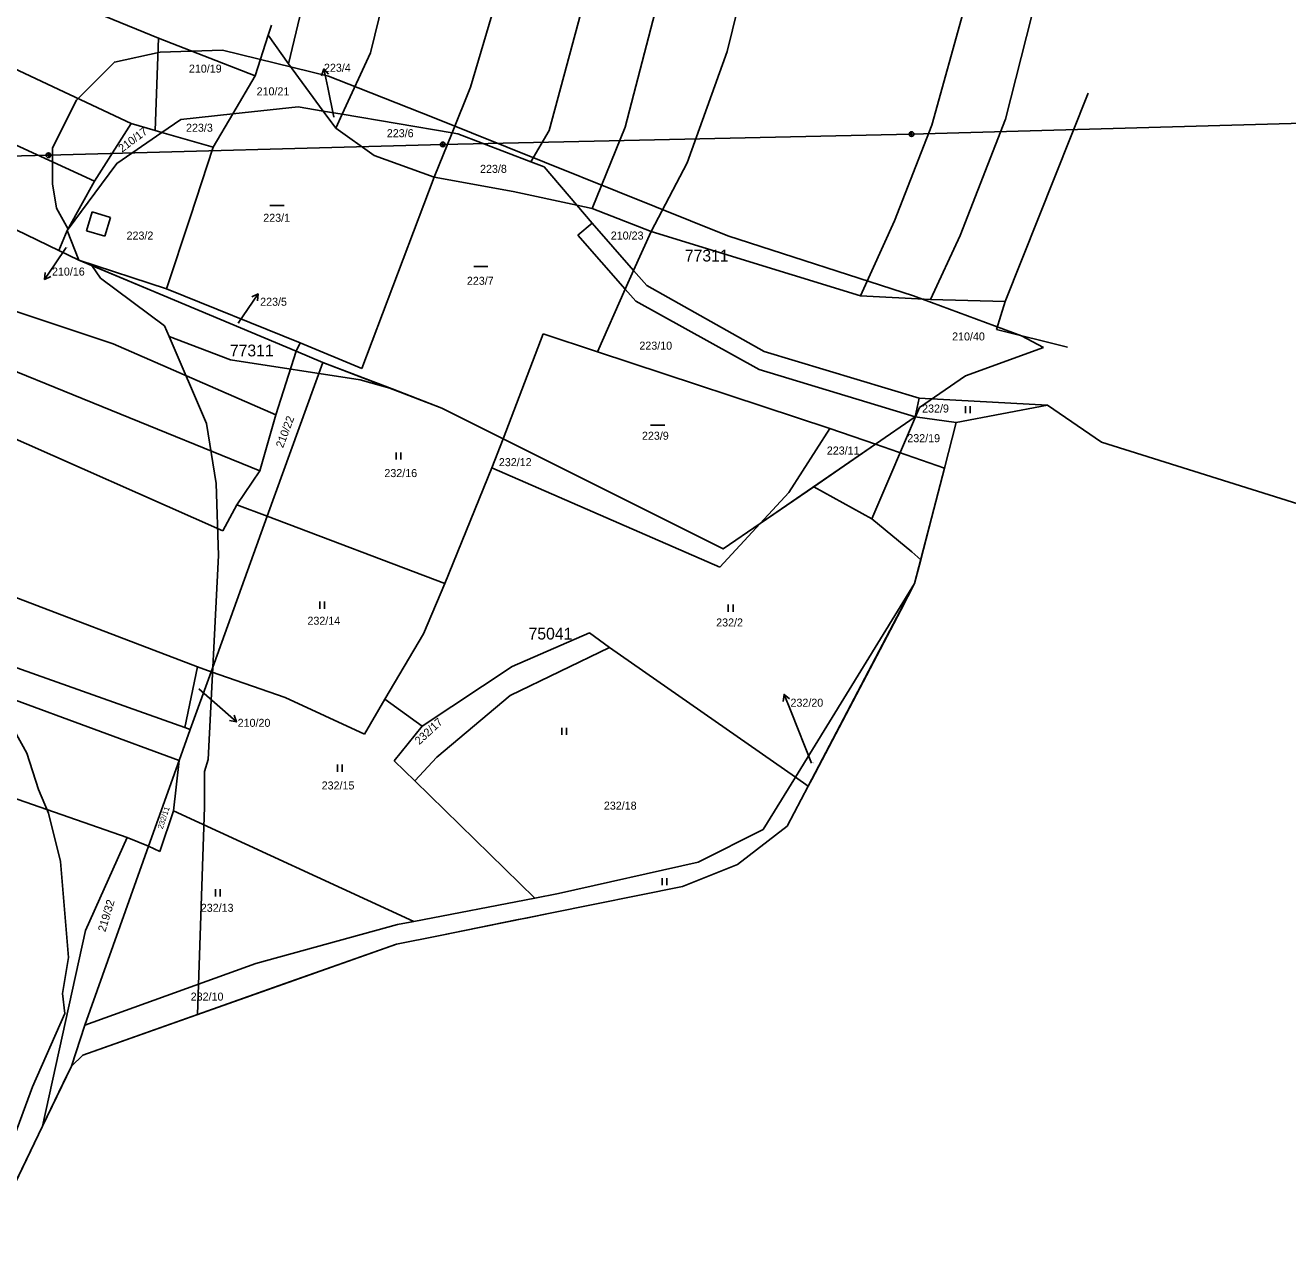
# Model space of a CAD drawing. Extents: x -743888 to -742027, y -1128394 to -1126768.
# Drawn here: x -742720.1 to -742452, y -1128049.6 to -1127789.2 of the extents above; entities that cross this region are included whole.
import ezdxf

# ---------------------------------------------------------------- set-up
doc = ezdxf.new("R2010")
doc.units = 0
for name, color, linetype in [('Vrstva 1', 7, 'Continuous'), ('Vrstva 12', 7, 'Continuous'), ('Vrstva 13', 7, 'Continuous'), ('Vrstva 16', 7, 'Continuous'), ('Vrstva 18', 7, 'Continuous'), ('Vrstva 25', 7, 'Continuous'), ('Vrstva 26', 7, 'Continuous'), ('Vrstva 4', 7, 'Continuous'), ('Vrstva 52', 7, 'Continuous'), ('Vrstva 53', 7, 'Continuous'), ('Vrstva 6', 7, 'Continuous')]:
    doc.layers.add(name, color=color, linetype=linetype)

msp = doc.modelspace()

# ---------------------------------------------------------------- linework, layer by layer
at = {"layer": 'Vrstva 1'}
for points in [[(-742675.99, -1127807.99), (-742662.11, -1127806.5)], [(-742662.11, -1127806.5), (-742656.82, -1127807.4)], [(-742691.07, -1127811.95), (-742687.04, -1127809.18)], [(-742687.04, -1127809.18), (-742675.99, -1127807.99)], [(-742656.82, -1127807.4), (-742652.76, -1127808.09)], [(-742652.76, -1127808.09), (-742629.43, -1127812.04)], [(-742700.65, -1127818.54), (-742691.07, -1127811.95)], [(-742629.43, -1127812.04), (-742628.23, -1127812.24)], [(-742628.23, -1127812.24), (-742612.72, -1127818.18)], [(-742703.9, -1127822.96), (-742700.65, -1127818.54)], [(-742612.72, -1127818.18), (-742609.89, -1127819.27)], [(-742609.89, -1127819.27), (-742602.93, -1127827.4)], [(-742711.14, -1127832.79), (-742703.9, -1127822.96)], [(-742602.93, -1127827.4), (-742599.66, -1127831.22)], [(-742711.14, -1127832.79), (-742708.67, -1127839.06)], [(-742599.66, -1127831.22), (-742590.87, -1127841.26)], [(-742708.67, -1127839.06), (-742690.54, -1127846.66)], [(-742590.87, -1127841.26), (-742588.09, -1127844.43)], [(-742588.09, -1127844.43), (-742563.17, -1127858.44)], [(-742690.54, -1127846.66), (-742662.54, -1127858.41)], [(-742662.54, -1127858.41), (-742656.86, -1127860.79)], [(-742563.17, -1127858.44), (-742530.23, -1127868.37)], [(-742668.67, -1127893.45), (-742656.86, -1127860.79)], [(-742656.86, -1127860.79), (-742631.6, -1127870.48)], [(-742531.05, -1127872.36), (-742530.23, -1127868.37)], [(-742530.23, -1127868.37), (-742503.01, -1127869.85)], [(-742631.6, -1127870.48), (-742618.61, -1127876.98)], [(-742539.51, -1127878.17), (-742531.05, -1127872.36)], [(-742531.05, -1127872.36), (-742522.38, -1127873.53)], [(-742618.61, -1127876.98), (-742571.86, -1127900.4)], [(-742564.03, -1127895.02), (-742539.51, -1127878.17)], [(-742680.6, -1127926.45), (-742668.67, -1127893.45)], [(-742571.86, -1127900.4), (-742564.03, -1127895.02)], [(-742802.25, -1127897.14), (-742686.17, -1127938.31)], [(-742556.49, -1127948.86), (-742531.2, -1127907.76)], [(-742685.04, -1127938.71), (-742680.6, -1127926.45)], [(-742686.17, -1127938.31), (-742685.04, -1127938.71)], [(-742687.4, -1127945.34), (-742685.04, -1127938.71)], [(-742693.88, -1127963.5), (-742687.4, -1127945.34)], [(-742563.33, -1127959.98), (-742556.49, -1127948.86)], [(-742577.15, -1127966.9), (-742563.33, -1127959.98)], [(-742707.43, -1128001.51), (-742693.88, -1127963.5)], [(-742606.85, -1127973.58), (-742577.15, -1127966.9)], [(-742637.54, -1127979.49), (-742611.87, -1127974.55)], [(-742611.87, -1127974.55), (-742606.85, -1127973.58)], [(-742671.12, -1127988.44), (-742641.03, -1127980.16)], [(-742641.03, -1127980.16), (-742637.54, -1127979.49)], [(-742707.43, -1128001.51), (-742671.12, -1127988.44)], [(-742710.24, -1128010.19), (-742707.43, -1128001.51)]]:
    msp.add_lwpolyline(points, dxfattribs=at)
at = {"layer": 'Vrstva 12'}
for points in [[(-742433.58, -1127809.53), (-742531.86, -1127812.3)], [(-742631.4, -1127814.49), (-742531.86, -1127812.3)], [(-742715.13, -1127816.8), (-742631.4, -1127814.49)], [(-742821.14, -1127819.37), (-742715.13, -1127816.8)]]:
    msp.add_lwpolyline(points, dxfattribs=at)
at = {"layer": 'Vrstva 13'}
for p, q in [((-742531.2, -1127907.76), (-742524.88, -1127883.24)), ((-742553.06, -1127949.33), (-742534.15, -1127913.36)), ((-742608.61, -1127977.73), (-742580.51, -1127972.05)), ((-742707.81, -1128007.87), (-742641.25, -1127984.32)), ((-742728.18, -1128047.33), (-742716.39, -1128022.92))]:
    msp.add_line(p, q, dxfattribs=at)
for points in [[(-742522.38, -1127873.53), (-742503.01, -1127869.85)], [(-742524.88, -1127883.24), (-742522.38, -1127873.53)], [(-742534.15, -1127913.36), (-742531.2, -1127907.76)], [(-742558.28, -1127959.25), (-742553.8, -1127950.73)], [(-742553.8, -1127950.73), (-742553.06, -1127949.33)], [(-742568.84, -1127967.38), (-742558.28, -1127959.25)], [(-742580.51, -1127972.05), (-742568.84, -1127967.38)], [(-742632.32, -1127982.52), (-742608.61, -1127977.73)], [(-742641.25, -1127984.32), (-742632.32, -1127982.52)], [(-742710.24, -1128010.19), (-742707.81, -1128007.87)], [(-742716.39, -1128022.92), (-742710.24, -1128010.19)]]:
    msp.add_lwpolyline(points, dxfattribs=at)
at = {"layer": 'Vrstva 16'}
for p, q in [((-742657.12, -1127799.9), (-742656.65, -1127798.47)), ((-742714.6, -1127842.52), (-742715.95, -1127843.17)), ((-742671.96, -1127846.87), (-742670.61, -1127846.22)), ((-742559.14, -1127932.75), (-742558.93, -1127931.27)), ((-742675.69, -1127935.7), (-742675.21, -1127937.12))]:
    msp.add_line(p, q, dxfattribs=at)
for points in [[(-742655.84, -1127802.39), (-742656.65, -1127798.47), (-742655.65, -1127799.59)], [(-742654.53, -1127808.7), (-742655.84, -1127802.39)], [(-742711.38, -1127836.41), (-742713.71, -1127839.86)], [(-742713.71, -1127839.86), (-742715.95, -1127843.17), (-742715.84, -1127841.68)], [(-742672.86, -1127849.53), (-742670.61, -1127846.22), (-742670.72, -1127847.72)], [(-742674.85, -1127852.46), (-742672.86, -1127849.53)], [(-742683.2, -1127930.09), (-742678.21, -1127934.48)], [(-742557.44, -1127934.98), (-742558.93, -1127931.27), (-742557.75, -1127932.19)], [(-742678.21, -1127934.48), (-742675.21, -1127937.12), (-742676.68, -1127936.83)], [(-742553.07, -1127945.89), (-742557.44, -1127934.98)]]:
    msp.add_lwpolyline(points, dxfattribs=at)
at = {"layer": 'Vrstva 25'}
for p, q in [((-742668.11, -1127827.45), (-742665.11, -1127827.45)), ((-742624.81, -1127840.39), (-742621.81, -1127840.39)), ((-742520.37, -1127870.09), (-742520.37, -1127871.59)), ((-742519.37, -1127871.59), (-742519.37, -1127870.09)), ((-742587.26, -1127874.09), (-742584.26, -1127874.09)), ((-742641.29, -1127879.92), (-742641.29, -1127881.42)), ((-742640.29, -1127881.42), (-742640.29, -1127879.92)), ((-742657.54, -1127911.58), (-742657.54, -1127913.08)), ((-742656.54, -1127913.08), (-742656.54, -1127911.58)), ((-742570.76, -1127912.21), (-742570.76, -1127913.71)), ((-742569.76, -1127913.71), (-742569.76, -1127912.21)), ((-742606.12, -1127938.36), (-742606.12, -1127939.86)), ((-742605.12, -1127939.86), (-742605.12, -1127938.36)), ((-742653.74, -1127946.19), (-742653.74, -1127947.69)), ((-742652.74, -1127947.69), (-742652.74, -1127946.19)), ((-742584.81, -1127970.31), (-742584.81, -1127971.81)), ((-742583.81, -1127971.81), (-742583.81, -1127970.31)), ((-742679.68, -1127972.66), (-742679.68, -1127974.16)), ((-742678.68, -1127974.16), (-742678.68, -1127972.66))]:
    msp.add_line(p, q, dxfattribs=at)
at = {"layer": 'Vrstva 26'}
for p, q in [((-742532.32, -1127812.48), (-742531.68, -1127811.84)), ((-742532.06, -1127812.75), (-742531.41, -1127812.1)), ((-742631.86, -1127814.67), (-742631.21, -1127814.03)), ((-742631.6, -1127814.94), (-742630.95, -1127814.29)), ((-742715.59, -1127816.98), (-742714.95, -1127816.34)), ((-742715.33, -1127817.25), (-742714.68, -1127816.6))]:
    msp.add_line(p, q, dxfattribs=at)
for centre in [(-742531.86, -1127812.3), (-742631.4, -1127814.49), (-742715.13, -1127816.8)]:
    msp.add_circle(centre, 0.5, dxfattribs=at)
at = {"layer": 'Vrstva 4'}
for points in [[(-742707.09, -1127832.82), (-742705.88, -1127828.82)], [(-742705.88, -1127828.82), (-742701.93, -1127830.01)], [(-742703.14, -1127834.01), (-742701.93, -1127830.01)], [(-742707.09, -1127832.82), (-742703.14, -1127834.01)], [(-742602.7, -1127833.78), (-742599.66, -1127831.22)], [(-742602.7, -1127833.78), (-742592.64, -1127845.23)], [(-742592.64, -1127845.23), (-742590.38, -1127847.8)], [(-742590.38, -1127847.8), (-742564.19, -1127862.31)], [(-742564.19, -1127862.31), (-742531.05, -1127872.36)]]:
    msp.add_lwpolyline(points, dxfattribs=at)
at = {"layer": 'Vrstva 52'}
for points in [[(-742503.81, -1127857.63), (-742508.5, -1127855.13), (-742531.44, -1127846.63), (-742570.88, -1127833.88), (-742633.25, -1127808.88), (-742649.38, -1127802.5), (-742655.69, -1127800), (-742678.19, -1127794.5), (-742691.38, -1127794.88), (-742701.13, -1127797), (-742709.19, -1127805.13), (-742714.25, -1127815.25), (-742714.25, -1127822.88), (-742713.44, -1127828), (-742710.93, -1127832.5)], [(-742710.93, -1127832.5), (-742703.9, -1127822.96), (-742700.65, -1127818.54), (-742691.07, -1127811.95), (-742687.04, -1127809.18), (-742675.99, -1127807.99), (-742662.11, -1127806.5), (-742656.82, -1127807.4), (-742652.76, -1127808.09), (-742629.43, -1127812.04), (-742628.23, -1127812.24), (-742612.72, -1127818.18), (-742609.89, -1127819.27), (-742602.93, -1127827.4), (-742599.66, -1127831.22), (-742590.87, -1127841.26), (-742588.09, -1127844.43), (-742563.17, -1127858.44), (-742530.23, -1127868.37), (-742531.05, -1127872.36), (-742539.51, -1127878.17), (-742552.6, -1127887.17)], [(-742710.93, -1127832.5), (-742711.14, -1127832.79), (-742708.67, -1127839.06), (-742705.95, -1127840.2)], [(-742705.95, -1127840.2), (-742704.06, -1127842.88), (-742690.5, -1127853), (-742689.53, -1127855.25)], [(-742705.95, -1127840.2), (-742690.54, -1127846.66), (-742662.54, -1127858.41), (-742656.86, -1127860.79), (-742642.18, -1127866.42)], [(-742689.53, -1127855.25), (-742676.5, -1127860.25), (-742648.94, -1127864.5), (-742642.18, -1127866.42)], [(-742683.48, -1127999.26), (-742682, -1127955.25), (-742682, -1127947.63), (-742681.19, -1127945.13), (-742679.06, -1127901.75), (-742679.5, -1127886.5), (-742681.56, -1127873.75), (-742689.53, -1127855.25)], [(-742540.25, -1127894), (-742530.13, -1127870.38), (-742520.38, -1127863.63), (-742503.81, -1127857.63)], [(-742642.18, -1127866.42), (-742631.6, -1127870.48), (-742618.61, -1127876.98), (-742571.86, -1127900.4), (-742564.03, -1127895.02), (-742552.6, -1127887.17)], [(-742529.9, -1127902.7), (-742524.88, -1127883.24), (-742522.38, -1127873.53), (-742503.01, -1127869.85), (-742491.5, -1127877.75), (-742426.38, -1127898.15), (-742397.46, -1127907.21), (-742391.19, -1127889.54)], [(-742552.6, -1127887.17), (-742540.25, -1127894)], [(-742540.25, -1127894), (-742531.81, -1127901), (-742529.9, -1127902.7)], [(-742683.48, -1127999.26), (-742666.12, -1127993.12), (-742641.25, -1127984.32), (-742632.32, -1127982.52), (-742615.39, -1127979.1), (-742613.69, -1127978.76), (-742608.61, -1127977.73), (-742580.51, -1127972.05), (-742575.53, -1127970.06), (-742568.84, -1127967.38), (-742558.28, -1127959.25), (-742553.8, -1127950.73), (-742531.2, -1127907.76), (-742529.9, -1127902.7)], [(-742725.31, -1127933.63), (-742719.75, -1127943.75), (-742717.25, -1127951.5), (-742715.13, -1127956.5), (-742712.56, -1127966.75), (-742710.88, -1127987.13), (-742712.13, -1127994.75), (-742711.69, -1127999), (-742718.5, -1128014.63), (-742722.75, -1128026.13)], [(-742729.71, -1128049.62), (-742728.18, -1128047.33), (-742716.39, -1128022.92), (-742711.15, -1128012.08), (-742710.24, -1128010.19), (-742707.81, -1128007.87), (-742683.48, -1127999.26)]]:
    msp.add_lwpolyline(points, dxfattribs=at)
at = {"layer": 'Vrstva 6'}
for points in [[(-742625.54, -1127802.36), (-742595.59, -1127701.21)], [(-742664.19, -1127797.36), (-742650.2, -1127739.03)], [(-742608.79, -1127811.54), (-742589.16, -1127738.55)], [(-742592.67, -1127810.85), (-742575.45, -1127744.63)], [(-742786.9, -1127753.03), (-742691.75, -1127791.9)], [(-742646.74, -1127795.08), (-742636.01, -1127751.08)], [(-742511.87, -1127809.1), (-742499.62, -1127760.84)], [(-742571.03, -1127794.76), (-742564.08, -1127766.54)], [(-742527.52, -1127810.4), (-742520.53, -1127785.2)], [(-742668.48, -1127791.31), (-742667.79, -1127789.16)], [(-742692.45, -1127811.55), (-742691.75, -1127791.9)], [(-742691.75, -1127791.9), (-742671.24, -1127799.9)], [(-742671.24, -1127799.9), (-742668.48, -1127791.31)], [(-742668.48, -1127791.31), (-742664.19, -1127797.36)], [(-742652.76, -1127808.09), (-742646.74, -1127795.08)], [(-742579.48, -1127818.4), (-742571.03, -1127794.76)], [(-742723.74, -1127797.75), (-742697.57, -1127810.08)], [(-742664.19, -1127797.36), (-742656.82, -1127807.4)], [(-742752.11, -1127800.85), (-742705.33, -1127822.31)], [(-742675.99, -1127807.99), (-742671.24, -1127799.9)], [(-742629.43, -1127812.04), (-742625.54, -1127802.36)], [(-742511.96, -1127847.84), (-742494.32, -1127803.6)], [(-742777.16, -1127805.95), (-742712.92, -1127837.01)], [(-742680.15, -1127815.09), (-742675.99, -1127807.99)], [(-742656.82, -1127807.4), (-742654.13, -1127811.06)], [(-742654.13, -1127811.06), (-742652.76, -1127808.09)], [(-742521.5, -1127833.81), (-742511.87, -1127809.1)], [(-742705.33, -1127822.31), (-742697.57, -1127810.08)], [(-742697.57, -1127810.08), (-742692.45, -1127811.55)], [(-742692.45, -1127811.55), (-742691.07, -1127811.95)], [(-742691.07, -1127811.95), (-742680.15, -1127815.09)], [(-742654.13, -1127811.06), (-742645.94, -1127816.84)], [(-742633.23, -1127821.48), (-742629.43, -1127812.04)], [(-742612.72, -1127818.18), (-742608.79, -1127811.54)], [(-742599.71, -1127828.08), (-742592.67, -1127810.85)], [(-742535.44, -1127830.74), (-742527.52, -1127810.4)], [(-742685.06, -1127830.02), (-742680.15, -1127815.09)], [(-742645.94, -1127816.84), (-742633.23, -1127821.48)], [(-742587.17, -1127832.97), (-742579.48, -1127818.4)], [(-742711.14, -1127832.79), (-742705.33, -1127822.31)], [(-742648.57, -1127862.05), (-742633.23, -1127821.48)], [(-742633.23, -1127821.48), (-742616.47, -1127824.52)], [(-742616.47, -1127824.52), (-742602.93, -1127827.4)], [(-742602.93, -1127827.4), (-742599.71, -1127828.08)], [(-742599.71, -1127828.08), (-742587.17, -1127832.97)], [(-742690.04, -1127845.16), (-742685.06, -1127830.02)], [(-742542.71, -1127846.65), (-742535.44, -1127830.74)], [(-742712.92, -1127837.01), (-742711.14, -1127832.79)], [(-742590.87, -1127841.26), (-742587.17, -1127832.97)], [(-742587.17, -1127832.97), (-742542.71, -1127846.65)], [(-742527.8, -1127847.44), (-742521.5, -1127833.81)], [(-742712.92, -1127837.01), (-742708.67, -1127839.06)], [(-742708.67, -1127839.06), (-742690.04, -1127845.16)], [(-742592.64, -1127845.23), (-742590.87, -1127841.26)], [(-742690.04, -1127845.16), (-742661.69, -1127856.62)], [(-742598.57, -1127858.52), (-742592.64, -1127845.23)], [(-742542.71, -1127846.65), (-742527.8, -1127847.44)], [(-742724.3, -1127849.19), (-742701.43, -1127856.81)], [(-742527.8, -1127847.44), (-742511.96, -1127847.84)], [(-742513.81, -1127853.78), (-742511.96, -1127847.84)], [(-742618.61, -1127876.98), (-742610.06, -1127854.73)], [(-742610.06, -1127854.73), (-742598.57, -1127858.52)], [(-742513.81, -1127853.78), (-742498.72, -1127857.52)], [(-742733.59, -1127858.01), (-742670.28, -1127883.77)], [(-742701.43, -1127856.81), (-742666.84, -1127871.89)], [(-742662.54, -1127858.41), (-742661.69, -1127856.62)], [(-742661.69, -1127856.62), (-742648.57, -1127862.05)], [(-742666.84, -1127871.89), (-742662.54, -1127858.41)], [(-742598.57, -1127858.52), (-742549.19, -1127874.82)], [(-742670.28, -1127883.77), (-742666.84, -1127871.89)], [(-742813.75, -1127875.71), (-742683.5, -1127925.44)], [(-742726.08, -1127875.32), (-742678.13, -1127896.57)], [(-742557.92, -1127888.41), (-742549.19, -1127874.82)], [(-742549.19, -1127874.82), (-742539.51, -1127878.17)], [(-742620.99, -1127883.17), (-742618.61, -1127876.98)], [(-742539.51, -1127878.17), (-742524.88, -1127883.24)], [(-742675.1, -1127891.02), (-742670.28, -1127883.77)], [(-742630.99, -1127907.7), (-742620.99, -1127883.17)], [(-742620.99, -1127883.17), (-742572.56, -1127904.25)], [(-742564.03, -1127895.02), (-742557.92, -1127888.41)], [(-742678.13, -1127896.57), (-742675.1, -1127891.02)], [(-742675.1, -1127891.02), (-742668.67, -1127893.45)], [(-742668.67, -1127893.45), (-742630.99, -1127907.7)], [(-742572.56, -1127904.25), (-742564.03, -1127895.02)], [(-742795.76, -1127905.39), (-742687.4, -1127945.34)], [(-742635.51, -1127918.42), (-742630.99, -1127907.7)], [(-742643.67, -1127932.31), (-742635.51, -1127918.42)], [(-742616.69, -1127925.34), (-742600.23, -1127918.18)], [(-742600.23, -1127918.18), (-742596.01, -1127921.34)], [(-742617.12, -1127931.51), (-742596.01, -1127921.34)], [(-742596.01, -1127921.34), (-742556.49, -1127948.86)], [(-742686.17, -1127938.31), (-742683.5, -1127925.44)], [(-742683.5, -1127925.44), (-742680.6, -1127926.45)], [(-742680.6, -1127926.45), (-742664.9, -1127931.91)], [(-742635.75, -1127937.99), (-742616.69, -1127925.34)], [(-742664.9, -1127931.91), (-742648.02, -1127939.7)], [(-742648.02, -1127939.7), (-742643.67, -1127932.31)], [(-742643.67, -1127932.31), (-742635.75, -1127937.99)], [(-742632.63, -1127944.62), (-742617.12, -1127931.51)], [(-742775.86, -1127934.72), (-742698.39, -1127961.68)], [(-742641.69, -1127945.38), (-742635.75, -1127937.99)], [(-742688.57, -1127956.03), (-742687.4, -1127945.34)], [(-742641.69, -1127945.38), (-742637.32, -1127949.65)], [(-742637.32, -1127949.65), (-742632.63, -1127944.62)], [(-742556.49, -1127948.86), (-742553.8, -1127950.73)], [(-742637.32, -1127949.65), (-742611.87, -1127974.55)], [(-742691.48, -1127964.62), (-742688.57, -1127956.03)], [(-742688.57, -1127956.03), (-742637.54, -1127979.49)], [(-742707.26, -1127981.44), (-742698.39, -1127961.68)], [(-742698.39, -1127961.68), (-742693.88, -1127963.5)], [(-742693.88, -1127963.5), (-742691.48, -1127964.62)], [(-742716.39, -1128022.92), (-742707.26, -1127981.44)]]:
    msp.add_lwpolyline(points, dxfattribs=at)

# ---------------------------------------------------------------- texts
at = {"layer": 'Vrstva 16'}
for s, p in [('223/4', (-742656.63, -1127799.06)), ('210/16', (-742714.39, -1127842.34)), ('223/5', (-742670.18, -1127848.75)), ('232/20', (-742557.56, -1127933.89)), ('210/20', (-742674.96, -1127938.16))]:
    msp.add_text(s, height=1.7, dxfattribs=at).set_placement(p)
at = {"layer": 'Vrstva 18'}
for s, height, p in [('210/19', 1.7, (-742685.31, -1127799.25)), ('210/21', 1.7, (-742670.93, -1127804.08)), ('223/4', 0.1, (-742654.53, -1127808.7)), ('223/3', 1.7, (-742685.92, -1127811.8)), ('223/6', 1.7, (-742643.28, -1127812.96)), ('223/8', 1.7, (-742623.48, -1127820.53)), ('223/1', 1.7, (-742669.52, -1127830.92)), ('223/2', 1.7, (-742698.55, -1127834.7)), ('210/23', 1.7, (-742595.72, -1127834.69)), ('210/16', 0.1, (-742711.38, -1127836.41)), ('223/7', 1.7, (-742626.28, -1127844.3)), ('223/5', 0.1, (-742674.85, -1127852.46)), ('210/40', 1.7, (-742523.24, -1127856.12)), ('223/10', 1.7, (-742589.65, -1127858.07)), ('232/9', 1.7, (-742529.61, -1127871.42)), ('223/9', 1.7, (-742589.1, -1127877.2)), ('232/19', 1.7, (-742532.75, -1127877.72)), ('223/11', 1.7, (-742549.84, -1127880.34)), ('232/12', 1.7, (-742619.49, -1127882.81)), ('232/16', 1.7, (-742643.8, -1127885.13)), ('232/14', 1.7, (-742660.14, -1127916.48)), ('232/2', 1.7, (-742573.34, -1127916.85)), ('210/20', 0.1, (-742683.2, -1127930.09)), ('232/20', 0.1, (-742553.07, -1127945.89)), ('232/15', 1.7, (-742657.12, -1127951.46)), ('232/18', 1.7, (-742597.19, -1127955.74)), ('232/13', 1.7, (-742682.79, -1127977.44)), ('232/10', 1.7, (-742684.93, -1127996.29))]:
    msp.add_text(s, height=height, dxfattribs=at).set_placement(p)
for s, height, rotation, p in [('210/17', 1.7, 36.6524, (-742699.51, -1127816.25)), ('210/22', 1.7, 69.433, (-742665.33, -1127879.06)), ('232/17', 1.7, 42.6281, (-742636.39, -1127942.07)), ('232/11', 1.19, 71.8637, (-742690.88, -1127959.95)), ('219/32', 1.7, 73.193, (-742703.07, -1127981.82))]:
    msp.add_text(s, height=height, rotation=rotation, dxfattribs=at).set_placement(p)
at = {"layer": 'Vrstva 53'}
for s, p in [('77311', (-742580, -1127839.36)), ('77311', (-742676.61, -1127859.5)), ('75041', (-742613.18, -1127919.62))]:
    msp.add_text(s, height=2.5, dxfattribs=at).set_placement(p)

doc.saveas('drawing.dxf')
